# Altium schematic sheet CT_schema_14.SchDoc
size 145 x 119 mm
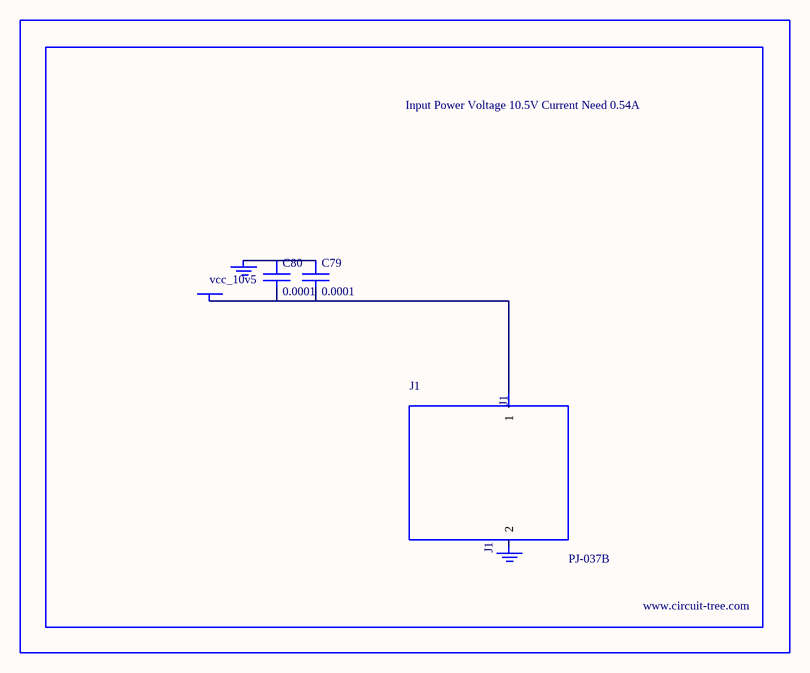
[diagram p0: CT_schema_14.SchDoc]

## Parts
BORDER13  (no value)
C79  0.0001  [EXV-9H]
C80  0.0001  [EXV-9H]
GND_INSTANCE_13_0  (no value)
GND_INSTANCE_13_1  (no value)
J1  PJ-037B  [PJ-037B_PACKAGE]
POWER_INSTANCE_13_0  vcc_10v5

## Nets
NetC79_1: C79.1 C80.1 GND_INSTANCE_13_0.0(GND)
NetC79_2: C79.2 C80.2 J1.1 POWER_INSTANCE_13_0.0(PWR)

Not connected (* = marked no-connect by the designer): GND_INSTANCE_13_1 0(GND); J1 2

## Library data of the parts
BORDER13 = BORDER_PAGE13
C79 C80 = EDK107M035A9HAA
GND_INSTANCE_13_0 GND_INSTANCE_13_1 = GND
POWER_INSTANCE_13_0 = PWR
